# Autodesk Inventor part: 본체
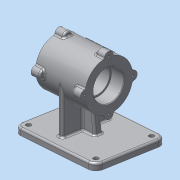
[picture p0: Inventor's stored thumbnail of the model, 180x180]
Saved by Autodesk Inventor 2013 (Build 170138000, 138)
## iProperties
Created: 2015-12
Part Number: 본체
Material: 알루미늄 6061
Document SubType Name: Modeling
Designer: dgall
Density: 2.71 g/cm^3
Mass: 1165.98 g
Surface Area: 820.012 cm^2
Volume: 430.252 cm^3
Author: dgall
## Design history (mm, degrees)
sketch "스케치1"
  geometry: L1 (0, 0)-(85, 0); L2 (0, 0)-(0, 37); L3 (0, 37)-(85, 37); L4 (85, 37)-(85, 0); L5 (0, 23.5)-(22, 23.5); L6 (22, 23.5)-(22, 21); L7 (22, 21)-(63, 21); L8 (63, 21)-(63, 23.5); L9 (63, 23.5)-(85, 23.5)
  constraints: 18 end point, 4 perpendicular, 2 parallel, 2 point on line, 1 collinear, 1 horizontal
  dimensions: "d0" = 85 distance of L1.start L1.end; "d1" = 47 diameter of L5 L1; "d2" = 47 diameter of L9 L1; "d3" = 42 diameter of L7 L1; "d4" = 74 diameter of L3 L1; "d6" = 22 distance of L5.start L5.end
revolve "회전1" sketch "스케치1" stored, may be unused: angle "d5" = 90 deg
node "작업 평면1"
sketch "스케치2"
  geometry: L1 (-122.5, 55)-(17.5, 55); L2 (17.5, 55)-(17.5, -55); L3 (17.5, -55)-(-122.5, -55); L4 (-122.5, -55)-(-122.5, 55); L5 (-85, 37)-(-85, -37) reference; L6 (0, 37)-(-85, 37) reference; 1 further point
  constraints: 8 end point, 2 parallel, 1 horizontal, 1 perpendicular
  dimensions: "d8" = 140 distance of L1.start L1.end; "d10" = 110 distance of L1.end L2.end; "d11" = 37.5 distance between parallel lines of L5 L4; "d12" = 18 distance between parallel lines of L6 L1
extrude "돌출1" join sketch "스케치2" distance "d13" = 10; taper "d14" = 0 deg
node "작업 평면2"
sketch "스케치3"
  geometry: L1 (55, -80)-(-55, -80) reference; L2 (55, -80)-(55, -70) reference; L3 (-55, -70)-(55, -70) reference; L4 (-55, -80)-(-55, -70) reference; L5 (-37, 0)-(-37, -70); L6 (-55, -70)-(55, -70) reference; L7 (37, 0)-(37, -70); A1 r 37 centre (0, 0) between (-37, 0) and (37, 0) reference; 1 further point
  constraints: 4 end point, 2 point on circle, 2 point on line, 2 tangent, 1 parallel, 1 perpendicular
extrude "돌출2" join sketch "스케치3" stored distance "d15" = 8; taper "d16" = 0 deg
sketch "스케치4"
  geometry: L1 (38.5, 0)-(38.5, 0) reference; L2 (38.5, 0)-(46.5, 0) reference; L3 (46.5, 0)-(46.5, 0) reference; L4 (38.5, 0)-(46.5, 0) reference; L5 (85, -37)-(85, 37) reference; L6 (0, -37)-(0, 37) reference; L7 (122.5, -70)-(-17.5, -70) reference; L8 (-17.5, -70)-(122.5, -70) reference; L9 (122.5, -80)-(-17.5, -80) reference; L10 (122.5, -80)-(122.5, -70) reference; L11 (-17.5, -70)-(122.5, -70) reference; L12 (-17.5, -80)-(-17.5, -70) reference; L13 (0, -37)-(85, -37) reference; L14 (42.5, -37)-(42.5, -70); L15 (38.5, -70)-(46.5, -70) reference; L16 (46.5, -70)-(46.5, 0) reference; L17 (38.5, 0)-(38.5, -70) reference; L18 (0, -37)-(85, -37) reference; L19 (22.839, -26.519)-(17.5, -70); L20 (62.161, -26.519)-(67.5, -70); L21 (22.839, -26.519)-(62.161, -26.519); 1 further point
  constraints: 8 end point, 2 midpoint, 2 point on line, 1 parallel
  dimensions: "d27" = 50 distance of L20.end L19.end; "d29" = 25 distance of L19.end L14.end; "d30" = 97 deg angle of L8 L19; "d31" = 97 deg angle of L7 L20; "d32" = 39.32231 distance of L19.start L20.start
extrude "돌출3" join sketch "스케치4" stored distance "d33" = 12; taper "d34" = 0 deg
fillet "모깎기1" dims "d35" = 12
hole "구멍1" diameter "d38" = 8; stored, may be unused: countersink angle "d42" = 90 deg, drill point angle "d44" = 0 deg; dims "d36" = 10, "d37" = 10, "d39" = 6, "d40" = 4, "d41" = 2, "d43" = 8
sketch "스케치5" dims "d51" = 14
  geometry: C1 r 23.5 at (0, 0) reference; 4 further points
  constraints: 3 vertical alignment, 2 horizontal alignment, 4 other
extrude "돌출4" join sketch "스케치5" distance "d52" = 15; taper "d53" = 0 deg
hole "구멍2" diameter "d56" = 3.459; stored, may be unused: countersink angle "d60" = 90 deg, drill point angle "d62" = 118 deg; dims "d54" = 10, "d55" = 10, "d57" = 9, "d58" = 4, "d59" = 2, "d61" = 11
node "작업 평면3"
fillet "모깎기2" dims "d66" = 3
fillet "모깎기3" dims "d67" = 3
fillet "모깎기4" dims "d68" = 3
fillet "모깎기5" dims "d71" = 3
chamfer "모따기1" distance "d72" = 1; stored, may be unused: second distance "d73" = 2, angle "d74" = 45 deg
fillet "모깎기6" dims "d75" = 0.3
node "작업 평면5"
  node "작업 평면4"
sketch "스케치6"
  geometry: L1 (-42.5, 18.921)-(-42.5, -18.921) reference; L2 (42.5, 18.921)-(42.5, -18.921) reference; 3 further points
  constraints: 1 horizontal alignment, 1 midpoint, 1 other
  dimensions: "d77" = 42.5 distance from line of point (0, 0) L1
feature "엠보싱1" sketch "스케치6" dims "d78" = 0.5, "d79" = 0
node "솔리드1"
pattern_linear "직사각형 패턴1" dims "d47" = 116, "d50" = 86
pattern_circular "원형 패턴1" dims angle "d64" = 360 deg
mirror "대칭1"
node "투영된 루프1"
node "투영된 루프2"
node "투영된 루프3"
other parameters: "d76" = -45 deg
